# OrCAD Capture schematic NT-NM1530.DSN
size A2; title: Nuvoton NT-NM1530; rev: 1.2; note: 8051 ISP-ICP Gang Programmer, ¥ÀªO.DSN
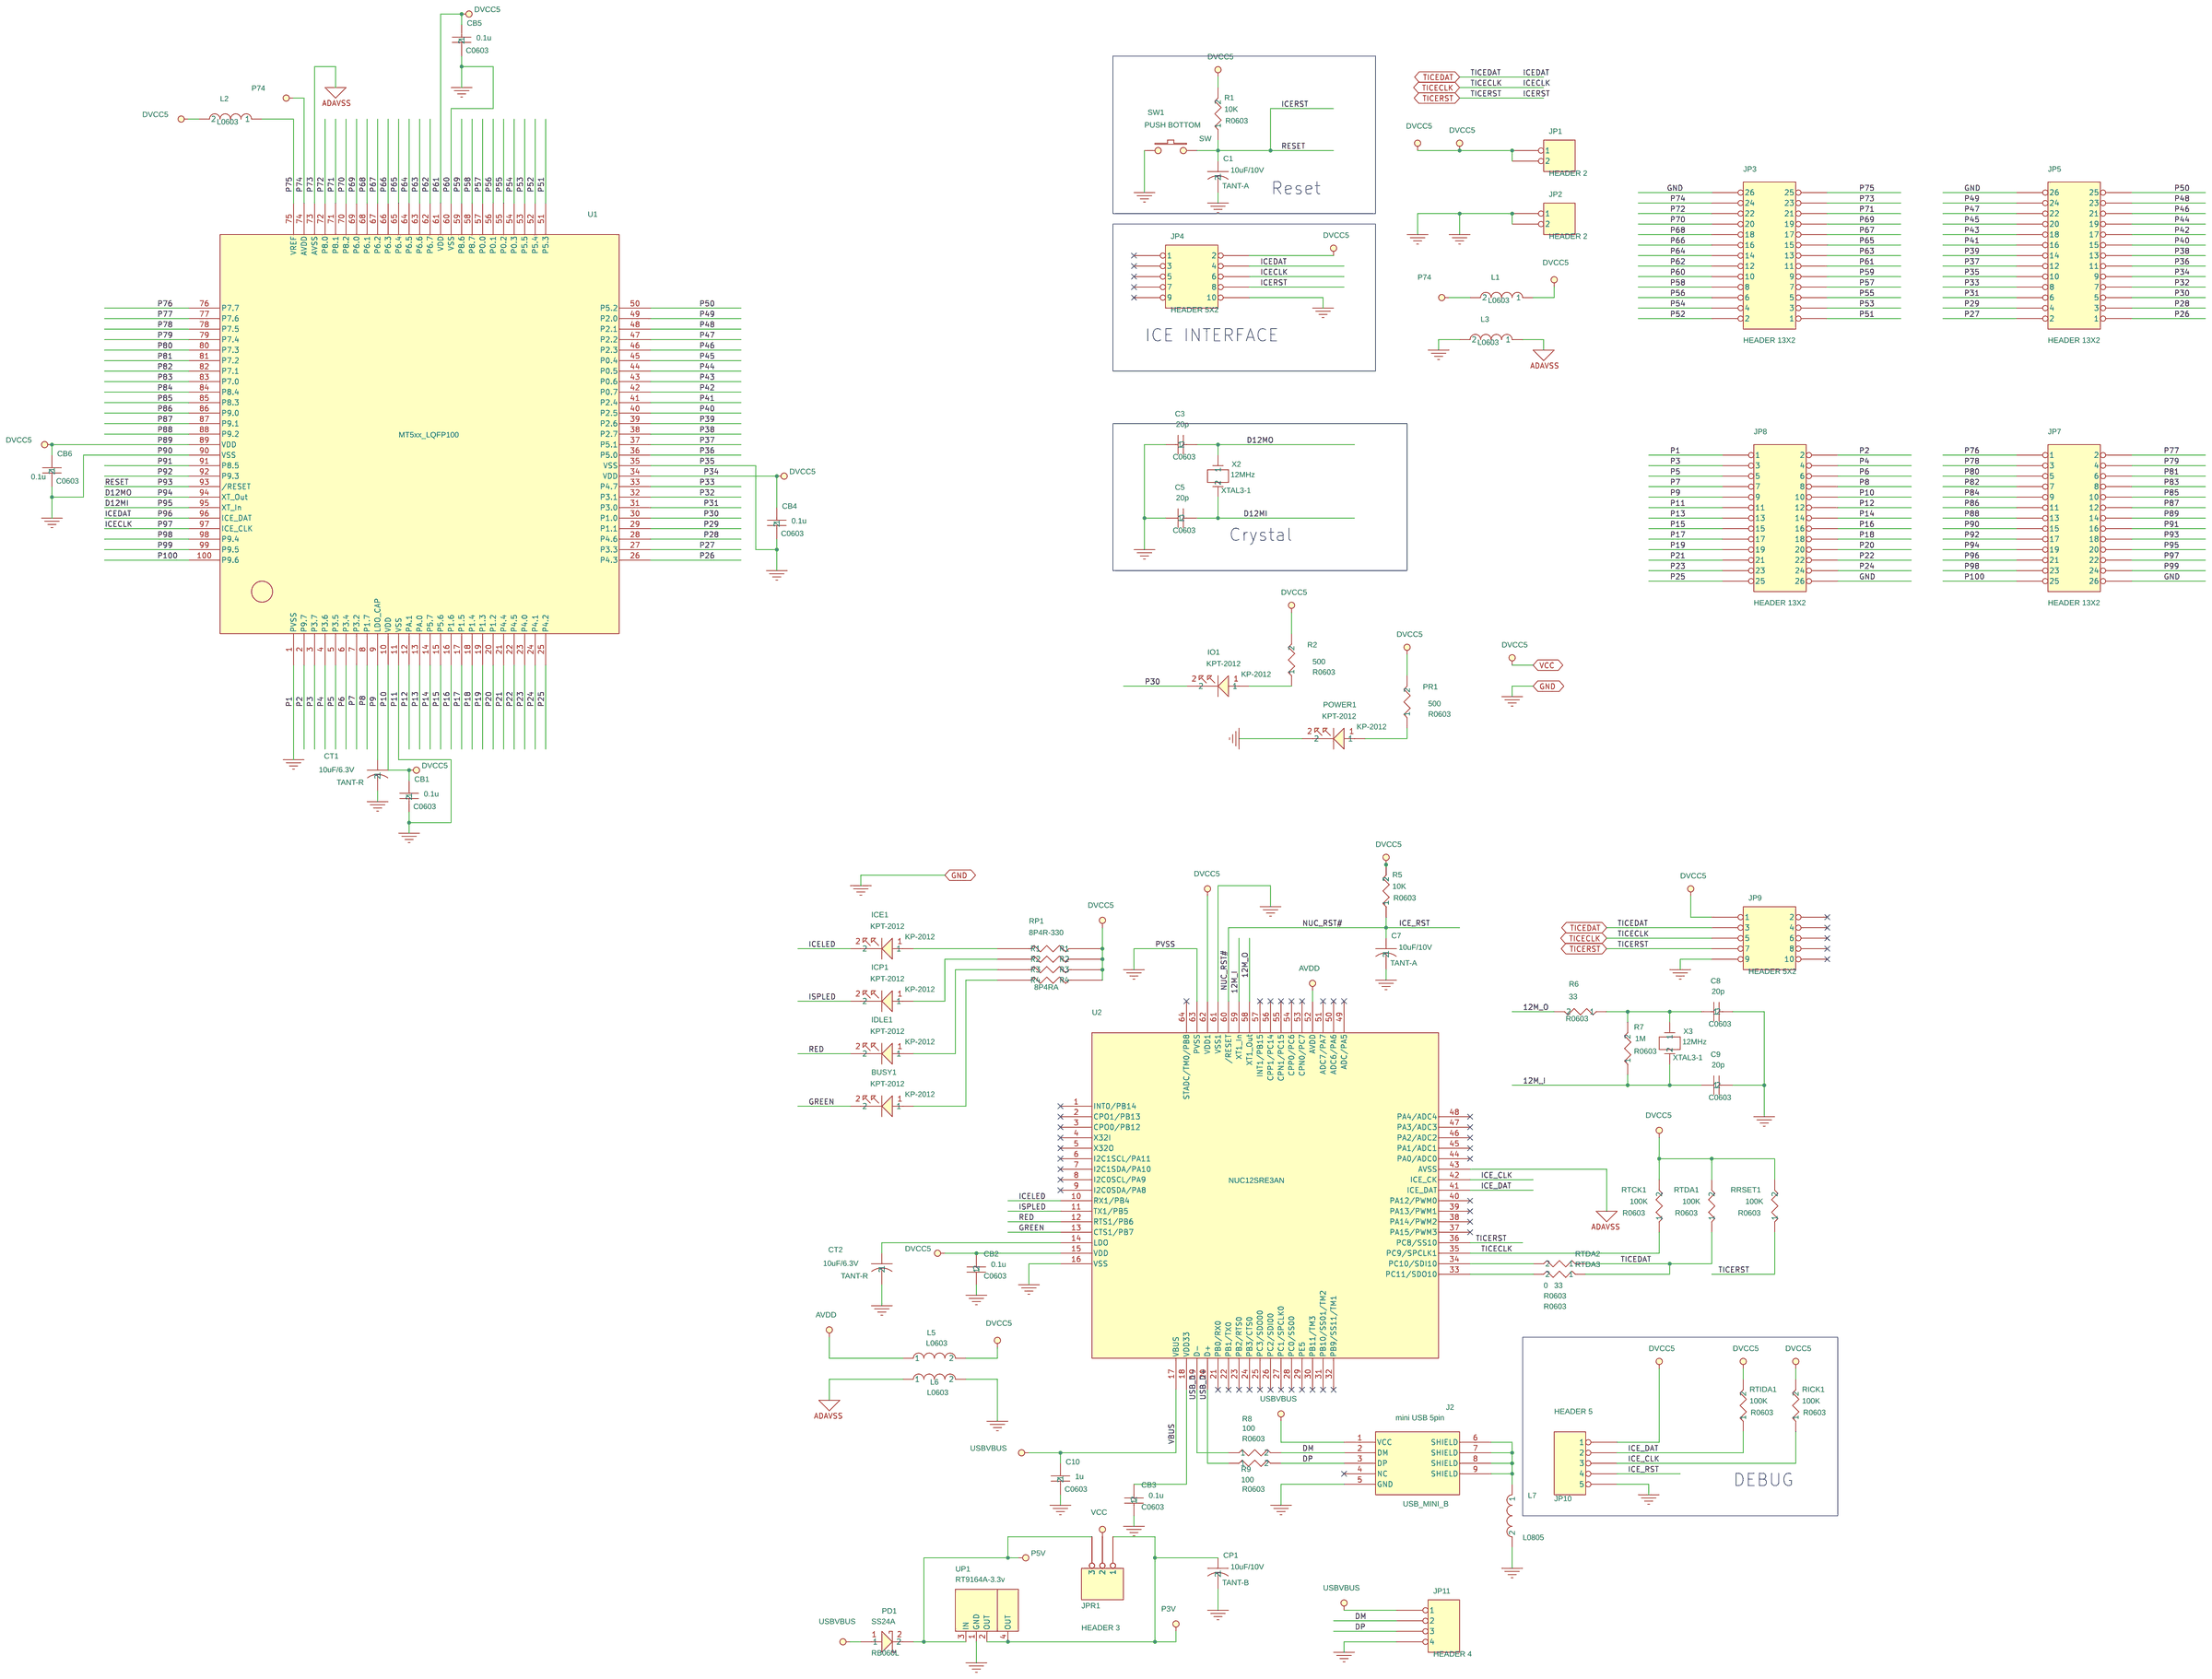
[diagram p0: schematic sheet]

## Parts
BUSY1  KPT-2012  [KP-2012]
C1  10uF/10V  [TANT-A]
C3  20p  [C0603]
C5  20p  [C0603]
C7  10uF/10V  [TANT-A]
C8  20p  [C0603]
C9  20p  [C0603]
C10  1u  [C0603]
CB1  0.1u  [C0603]
CB2  0.1u  [C0603]
CB3  0.1u  [C0603]
CB4  0.1u  [C0603]
CB5  0.1u  [C0603]
CB6  0.1u  [C0603]
CP1  10uF/10V  [TANT-B]
CT1  10uF/6.3V  [TANT-R]
CT2  10uF/6.3V  [TANT-R]
ICE1  KPT-2012  [KP-2012]
ICP1  KPT-2012  [KP-2012]
IDLE1  KPT-2012  [KP-2012]
IO1  KPT-2012  [KP-2012]
J2  mini USB 5pin  [USB_MINI_B]
JP1  HEADER 2
JP2  HEADER 2
JP3  HEADER 13X2
JP4  HEADER 5X2
JP5  HEADER 13X2
JP7  HEADER 13X2
JP8  HEADER 13X2
JP9  HEADER 5X2
JP10  HEADER 5
JP11  HEADER 4
JPR1  HEADER 3
L1  FERRITE BEAD  [L0603]
L2  FERRITE BEAD  [L0603]
L3  FERRITE BEAD  [L0603]
L5  FERRITE BEAD  [L0603]
L6  FERRITE BEAD  [L0603]
L7  FERRITE BEAD  [L0805]
PD1  SS24A  [RB060L]
POWER1  KPT-2012  [KP-2012]
PR1  500  [R0603]
R1  10K  [R0603]
R2  500  [R0603]
R5  10K  [R0603]
R6  33  [R0603]
R7  1M  [R0603]
R8  100  [R0603]
R9  100  [R0603]
RICK1  100K  [R0603]
RP1  8P4R-330  [8P4RA]
RRSET1  100K  [R0603]
RTCK1  100K  [R0603]
RTDA1  100K  [R0603]
RTDA2  0  [R0603]
RTDA3  33  [R0603]
RTIDA1  100K  [R0603]
SW1  PUSH BOTTOM  [SW]
U1  MT5xx_LQFP100
U2  NUC12SRE3AN  [NCU120_LQFP_64]
UP1  RT9164A-3.3v  [SOT-223-1]
X2  12MHz  [XTAL3-1]
X3  12MHz  [XTAL3-1]

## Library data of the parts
BUSY1 = LED_0_2: Vendor: Kingbright
C1 = CAP
C3 = CAP-C_10: Package: 0603
C5 = CAP-C_3: Package: 0603
C7 = CAP_3
C8 = CAP-C_9: Package: 0603
C9 = CAP-C_7: Package: 0603
C10 = CAP-C_2: Package: 0603
CB1 = CAP-C: Package: 0603
CB2 = CAP-C_8: Package: 0603
CB3 = CAP-C_6: Package: 0603
CB4 = CAP-C_4: Package: 0603
CB5 = CAP-C_1: Package: 0603
CB6 = CAP-C_5: Package: 0603
CP1 = CAP_2: Package: TANT-R
CT1 = CAP_1
CT2 = CAP_4
ICE1 = LED_0_1: Vendor: Kingbright
ICP1 = LED_0_4: Vendor: Kingbright
IDLE1 = LED_0_3: Vendor: Kingbright
IO1 = LED_0_5: Vendor: Kingbright
J2 = 4X1_HEADER_5
JP1 = HEADER_2
JP2 = HEADER_2_1
JP3 = HEADER_13X2
JP4 = HEADER_5X2_1
JP5 = HEADER_13X2_3
JP7 = HEADER_13X2_1
JP8 = HEADER_13X2_2
JP9 = HEADER_5X2
JP10 = HEADER_5
JP11 = HEADER_4
JPR1 = HEADER_3
L1 = INDUCTOR_4
L2 = INDUCTOR_5
L3 = INDUCTOR_3
L5 = INDUCTOR
L6 = INDUCTOR_2
L7 = INDUCTOR_1: Package: 0805
PD1 = DIODE_SCHOTTKY_6: Package: SOD-1231; Vendor: ROHM
POWER1 = LED_0: Vendor: Kingbright
PR1 = R_0_14: Package: 0603
R1 = R_0_12: Package: 0603
R2 = R_0_1: Package: 0603
R5 = R_0_10: Package: 0603
R6 = R_0_5: Package: 0603
R7 = R_0_7: Package: 0603
R8 = R_0_6: Package: 0603
R9 = R_0_11: Package: 0603
RICK1 = R_0_13: Package: 0603
RP1 = R-PACK8_0
RRSET1 = R_0_3: Package: 0603
RTCK1 = R_0_8: Package: 0603
RTDA1 = R_0: Package: 0603
RTDA2 = R_0_4: Package: 0603
RTDA3 = R_0_2: Package: 0603
RTIDA1 = R_0_9: Package: 0603
SW1 = SW_PUSHBUTTON: Package: DIP PUSH BOTTOM
U1 = MT5xx_LQFP100_0
U2 = NCU120_LQFP_64
UP1 = TO-247_Regulator_10
X2 = CRYSTAL
X3 = CRYSTAL_1

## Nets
AVDD: L5.1 U2.52(AVDD)
GND: C1.2 C3.1 C5.1 C7.2 C8.2 C9.2 C10.2 CB1.2 CB2.1 CB3.1 CB4.2 CB5.2 CB6.2 CP1.2 CT1.2 CT2.2 J2.5(GND) JP2.1 JP2.2 JP3.10 JP3.26 JP4.10 JP5.10 JP5.26 JP7.15 JP7.26 JP8.1 JP8.11 JP8.26 JP9.9 JP10.5 JP11.4 L3.2 L6.2 L7.2 POWER1.2 SW1.1 U1.1(PVSS) U1.11(VSS) U1.35(VSS) U1.60(VSS) U1.90(VSS) U2.16(VSS) U2.61(VSS1) U2.63(PVSS) UP1.1(GND)
P3V: CP1.1 JPR1.1 UP1.2(OUT) UP1.4(OUT)
P5V: JPR1.3 PD1.2 UP1.3(IN)
VCC: CB1.1 CB2.2 CB4.1 CB5.1 CB6.1 JP1.1 JP1.2 JP3.11 JP4.2 JP5.9 JP7.14 JP8.10 JP9.1 JP10.1 JPR1.2 L1.1 L2.2 L5.2 PR1.2 R1.2 R2.2 R5.2 RICK1.2 RP1.2(R1) RP1.4(R2) RP1.6(R3) RP1.8(R4) RRSET1.2 RTCK1.2 RTDA1.2 RTIDA1.2 U1.10(VDD) U1.34(VDD) U1.61(VDD) U1.89(VDD) U2.15(VDD) U2.62(VDD1)
12M_I: C9.1 R7.1 U2.59(XT1_In) X3.2
12M_O: R6.2 U2.58(XT1_Out)
ADAVSS: L6.1 U2.43(AVSS)
D12MI: C5.2 JP7.20 U1.95(XT_In) X2.2
D12MO: C3.2 JP7.19 U1.94(XT_Out) X2.1
DAVDD: JP3.24 L1.2 U1.74(AVDD)
DAVSS: JP3.23 L3.1 U1.73(AVSS)
DM: J2.2(DM) JP11.2 R8.2
DP: J2.3(DP) JP11.3 R9.2
GREEN: BUSY1.2 U2.13(CTS1/PB7)
ICE_CLK: JP10.3 RICK1.1 U2.42(ICE_CK)
ICE_DAT: JP10.2 RTIDA1.1 U2.41(ICE_DAT)
ICE_RST: C7.1 JP10.4 R5.1 U2.60(/RESET)
ICELED: ICE1.2 U2.10(RX1/PB4)
ISPLED: ICP1.2 U2.11(TX1/PB5)
P2: JP8.2 U1.2(P9.7)
P3: JP8.3 U1.3(P3.7)
P4: JP8.4 U1.4(P3.6)
P5: JP8.5 U1.5(P3.5)
P6: JP8.6 U1.6(P3.4)
P7: JP8.7 U1.7(P3.2)
P8: JP8.8 U1.8(P1.7)
P9: CT1.1 JP8.9 U1.9(LDO_CAP)
P12: JP8.12 U1.12(PA.1)
P13: JP8.13 U1.13(PA.0)
P14: JP8.14 U1.14(P5.7)
P15: JP8.15 U1.15(P5.6)
P16: JP8.16 U1.16(P1.6)
P17: JP8.17 U1.17(P1.5)
P18: JP8.18 U1.18(P1.4)
P19: JP8.19 U1.19(P1.3)
P20: JP8.20 U1.20(P1.2)
P21: JP8.21 U1.21(P4.4)
P22: JP8.22 U1.22(P4.5)
P23: JP8.23 U1.23(P4.0)
P24: JP8.24 U1.24(P4.1)
P25: JP8.25 U1.25(P4.2)
P26: JP5.1 U1.26(P4.3)
P27: JP5.2 U1.27(P3.3)
P28: JP5.3 U1.28(P4.6)
P29: JP5.4 U1.29(P1.1)
P30: IO1.2 JP5.5 U1.30(P1.0)
P31: JP5.6 U1.31(P3.0)
P32: JP5.7 U1.32(P3.1)
P33: JP5.8 U1.33(P4.7)
P36: JP5.11 U1.36(P5.0)
P37: JP5.12 U1.37(P5.1)
P38: JP5.13 U1.38(P2.7)
P39: JP5.14 U1.39(P2.6)
P40: JP5.15 U1.40(P2.5)
P41: JP5.16 U1.41(P2.4)
P42: JP5.17 U1.42(P0.7)
P43: JP5.18 U1.43(P0.6)
P44: JP5.19 U1.44(P0.5)
P45: JP5.20 U1.45(P0.4)
P46: JP5.21 U1.46(P2.3)
P47: JP5.22 U1.47(P2.2)
P48: JP5.23 U1.48(P2.1)
P49: JP5.24 U1.49(P2.0)
P50: JP5.25 U1.50(P5.2)
P51: JP3.1 U1.51(P5.3)
P52: JP3.2 U1.52(P5.4)
P53: JP3.3 U1.53(P5.5)
P54: JP3.4 U1.54(P0.3)
P55: JP3.5 U1.55(P0.2)
P56: JP3.6 U1.56(P0.1)
P57: JP3.7 U1.57(P0.0)
P58: JP3.8 U1.58(P8.7)
P59: JP3.9 U1.59(P8.6)
P62: JP3.12 U1.62(P6.7)
P63: JP3.13 U1.63(P6.6)
P64: JP3.14 U1.64(P6.5)
P65: JP3.15 U1.65(P6.4)
P66: JP3.16 U1.66(P6.3)
P67: JP3.17 U1.67(P6.2)
P68: JP3.18 U1.68(P6.1)
P69: JP3.19 U1.69(P6.0)
P70: JP3.20 U1.70(P8.2)
P71: JP3.21 U1.71(P8.1)
P72: JP3.22 U1.72(P8.0)
P75: JP3.25 L2.1 U1.75(VREF)
P76: JP7.1 U1.76(P7.7)
P77: JP7.2 U1.77(P7.6)
P78: JP7.3 U1.78(P7.5)
P79: JP7.4 U1.79(P7.4)
P80: JP7.5 U1.80(P7.3)
P81: JP7.6 U1.81(P7.2)
P82: JP7.7 U1.82(P7.1)
P83: JP7.8 U1.83(P7.0)
P84: JP7.9 U1.84(P8.4)
P85: JP7.10 U1.85(P8.3)
P86: JP7.11 U1.86(P9.0)
P87: JP7.12 U1.87(P9.1)
P88: JP7.13 U1.88(P9.2)
P91: JP7.16 U1.91(P8.5)
P92: JP7.17 U1.92(P9.3)
P98: JP7.23 U1.98(P9.4)
P99: JP7.24 U1.99(P9.5)
P100: JP7.25 U1.100(P9.6)
RED: IDLE1.2 U2.12(RTS1/PB6)
TICECLK: JP4.6 JP7.22 JP9.5 RTCK1.1 U1.97(ICE_CLK) U2.35(PC9/SPCLK1)
TICEDAT: JP4.4 JP7.21 JP9.3 RTDA1.1 RTDA2.1 RTDA3.1 U1.96(ICE_DAT)
TICERST: C1.1 JP4.8 JP7.18 JP9.7 R1.1 RRSET1.1 SW1.2 U1.93(/RESET) U2.36(PC8/SS10)
USB_D+: R9.1 U2.20(D+)
USB_D-: R8.1 U2.19(D-)
USBVBUS: C10.1 J2.1(VCC) JP11.1 PD1.1 U2.17(VBUS)
N16888435: POWER1.1 PR1.1
N16888673: IO1.1 R2.1
N16889742: J2.6(SHIELD) J2.7(SHIELD) J2.8(SHIELD) J2.9(SHIELD) L7.1
N16889816: RTDA2.2 U2.34(PC10/SDI10)
N16889832: CB3.2 U2.18(VDD33)
N16889847: IDLE1.1 RP1.5(R3)
N16889866: CT2.1 U2.14(LDO)
N16889870: BUSY1.1 RP1.7(R4)
N16889904: C8.1 R6.1 R7.2 X3.1
N16890312: ICE1.1 RP1.1(R1)
N16890465: ICP1.1 RP1.3(R2)
N16890546: RTDA3.2 U2.33(PC11/SDO10)

Not connected (* = marked no-connect by the designer): J2 4(NC)*; JP4 1* 3* 5* 7* 9*; JP9 2* 4* 6* 8* 10*; U2 1(INT0/PB14)* 2(CPO1/PB13)* 3(CPO0/PB12)* 4(X32I)* 5(X32O)* 6(I2C1SCL/PA11)* 7(I2C1SDA/PA10)* 8(I2C0SCL/PA9)* 9(I2C0SDA/PA8)* 21(PB0/RX0)* 22(PB1/TX0)* 23(PB2/RTS0)* 24(PB3/CTS0)* 25(PC3/SDO00)* 26(PC2/SDI00)* 27(PC1/SPCLK0)* 28(PC0/SS00)* 29(PE5)* 30(PB11/TM3)* 31(PB10/SS01/TM2)* 32(PB9/SS11/TM1)* 37(PA15/PWM3)* 38(PA14/PWM2)* 39(PA13/PWM1)* 40(PA12/PWM0)* 44(PA0/ADC0)* 45(PA1/ADC1)* 46(PA2/ADC2)* 47(PA3/ADC3)* 48(PA4/ADC4)* 49(ADC/PA5)* 50(ADC6/PA6)* 51(ADC7/PA7)* 53(CPN0/PC7)* 54(CPP0/PC6)* 55(CPN1/PC15)* 56(CPP1/PC14)* 57(INT1/PB15)* 64(STADC/TM0/PB8)*

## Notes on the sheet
- Reset
- ICE INTERFACE
- Crystal
- DEBUG
